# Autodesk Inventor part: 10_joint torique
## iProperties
Shininess: 20.0
Length Units: 11270
Angle Units: 11279
Time Units: 11290
Mass Units: 11283
Length Display Precision: 3
Angle Display Precision: 2
Created: 2000-10
Part Number: 10_joint torique
Material: Par défaut
Document SubType Name: Modélisation
Density: 0.0
Volumn: 0.0
Area: 0.0
PropertySet Name: Model Information
Control State: 0
Master: False
Checked Out: False
Author: Laurent GAUTHERON
